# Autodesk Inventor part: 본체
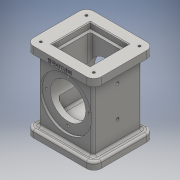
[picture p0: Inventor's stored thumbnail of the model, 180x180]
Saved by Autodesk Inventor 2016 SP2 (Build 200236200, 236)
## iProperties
Created: 2017-08
Part Number: 본체
Material: Generic
Document SubType Name: Modeling
Designer: Administrator
Density: 1 g/cm^3
Appearance: Default
Mass: 322.201 g
Surface Area: 648.794 cm^2
Volume: 322.201 cm^3
Author: Administrator
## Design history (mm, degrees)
sketch "스케치1"
  geometry: L1 (0, 0)-(92, 0); L2 (92, 0)-(92, -82); L3 (92, -82)-(0, -82); L4 (0, -82)-(0, 0)
  constraints: 8 end point, 2 parallel, 1 horizontal, 1 perpendicular
  dimensions: "d0" = 92 distance between parallel lines of L2 L4; "d1" = 82 distance between parallel lines of L3 L1
extrude "돌출1" new body sketch "스케치1" distance "d2" = 10; taper "d3" = 0 deg
sketch "스케치3"
  geometry: L1 (9, -8)-(83, -8); L2 (83, -8)-(83, -74); L3 (83, -74)-(9, -74); L4 (9, -74)-(9, -8); L5 (46, 14.875)-(46, -113.315); L6 (-13.466, -41)-(112.053, -41); L7 (92, 0)-(0, 0) reference; L8 (0, 0)-(0, -82) reference; 2 further points
  constraints: 12 end point, 2 horizontal, 2 midpoint, 2 parallel, 2 point on line, 1 perpendicular, 1 vertical, 2 other
  dimensions: "d6" = 74 distance between parallel lines of L2 L4; "d7" = 66 distance between parallel lines of L3 L1
extrude "돌출2" join sketch "스케치3" distance "d8" = 88; taper "d9" = 0 deg
sketch "스케치4"
  geometry: L1 (0, 0)-(0, -82) reference; L2 (92, -82)-(92, 0) reference; L3 (0, 0)-(92, 0); L4 (92, 0)-(92, -82); L5 (92, -82)-(0, -82); L6 (0, -82)-(0, 0)
  constraints: 8 end point, 2 parallel, 1 horizontal, 1 perpendicular
extrude "돌출3" join sketch "스케치4" distance "d10" = 10; taper "d11" = 0 deg
sketch "스케치5"
  geometry: L1 (-22, -65)-(-70, -65); L2 (-70, -65)-(-70, -17); L3 (-70, -17)-(-22, -17); L4 (-22, -17)-(-22, -65); L5 (-46, -97.263)-(-46, 16.227); L6 (13.409, -41)-(-111.741, -41); L7 (-92, -82)-(0, -82) reference; L8 (0, -82)-(0, 0) reference; 2 further points
  constraints: 12 end point, 2 horizontal, 2 midpoint, 2 parallel, 2 point on line, 1 perpendicular, 1 vertical, 2 other
  dimensions: "d12" = 48 distance between parallel lines of L2 L4; "d13" = 48 distance between parallel lines of L3 L1
extrude "돌출4" cut sketch "스케치5" distance "d14" = 16; taper "d15" = 0 deg
sketch "스케치6"
  geometry: L1 (83, -10)-(-9, -10) reference; C1 r 35 at (37, 44); 1 further point
  constraints: 1 centre point, 1 midpoint, 1 vertical alignment
  dimensions: "d16" = 70 diameter of C1; "d17" = 54 distance from line of L1 C1.centre
extrude "돌출5" cut sketch "스케치6" distance "d18" = 3; taper "d19" = 0 deg
sketch "스케치7"
  geometry: L1 (-9, 10)-(83, 10) reference; C1 r 35 at (37, -44); 1 further point
  constraints: 1 centre point, 1 midpoint, 1 vertical alignment
  dimensions: "d20" = 70 diameter of C1; "d21" = 54 distance from line of L1 C1.centre
extrude "돌출6" cut sketch "스케치7" distance "d22" = 3; taper "d23" = 0 deg
sketch "스케치8"
  geometry: L1 (46, -54)-(-46, -54) reference; C1 r 24 at (0, 2); 1 further point
  constraints: 1 centre point, 1 midpoint, 1 vertical alignment
  dimensions: "d24" = 48 diameter of C1; "d25" = 56 distance from line of L1 C1.centre
extrude "돌출7" cut sketch "스케치8" stored distance "d26" = 3; taper "d27" = 0 deg
sketch "스케치9"
  geometry: L1 (20, -15)-(72, -15); L2 (72, -15)-(72, -67); L3 (72, -67)-(20, -67); L4 (20, -67)-(20, -15); L5 (46, 9.933)-(46, -105.516); L6 (-12.497, -41)-(110.193, -41); L7 (92, 0)-(0, 0) reference; L8 (0, 0)-(0, -82) reference; 2 further points
  constraints: 12 end point, 2 horizontal, 2 midpoint, 2 parallel, 2 point on line, 1 perpendicular, 1 vertical, 2 other
  dimensions: "d28" = 52 distance between parallel lines of L3 L1; "d29" = 52 distance between parallel lines of L2 L4
extrude "돌출8" cut sketch "스케치9" distance "d30" = 8; taper "d31" = 0 deg
sketch "스케치10"
  geometry: L1 (24, -19)-(68, -19); L2 (68, -19)-(68, -63); L3 (68, -63)-(24, -63); L4 (24, -63)-(24, -19); L5 (46, 16.944)-(46, -107.049); L6 (-13.372, -41)-(115.449, -41); L7 (92, 0)-(0, 0) reference; L8 (0, 0)-(0, -82) reference; 2 further points
  constraints: 12 end point, 2 horizontal, 2 midpoint, 2 parallel, 2 point on line, 1 perpendicular, 1 vertical, 2 other
  dimensions: "d32" = 44 distance of L1.start L1.end; "d33" = 44 distance between parallel lines of L3 L1
extrude "돌출9" cut sketch "스케치10" distance "d34" = 74; taper "d35" = 0 deg
sketch "스케치12"
  geometry: L1 (46, -54)-(-46, -54) reference; A1 r 29 centre (0, 2) between (0, 31) and (29, 2); 3 further points
  constraints: 4 point on circle, 3 vertical alignment, 2 horizontal alignment, 1 centre point, 1 midpoint
  dimensions: "d36" = 58 diameter of A1; "d37" = 56 distance from line of L1 A1.centre
hole "구멍1" sketch "스케치12" at (0, 31), (29, 2), (-29, 2), (0, -27) diameter "d38" = 3.242; stored, may be unused: countersink angle "d42" = 90 deg, drill point angle "d44" = 118 deg; dims "d39" = 4, "d40" = 4, "d41" = 2, "d43" = 6
sketch "스케치13"
  geometry: L1 (-46, 54)-(46, 54) reference; C1 r 29 at (0, -2); C2 r 1.621 at (0, -31) reference; C3 r 1.621 at (-29, -2) reference; C4 r 1.621 at (29, -2) reference; C5 r 1.621 at (0, 27) reference; 5 further points
  constraints: 4 coincident, 1 centre point, 1 midpoint, 1 vertical alignment
  dimensions: "d45" = 58 diameter of C1; "d46" = 56 distance from line of L1 C1.centre
hole "구멍2" sketch "스케치13" at (0, -31), (-29, -2), (29, -2), (0, 27) diameter "d47" = 3.242; stored, may be unused: countersink angle "d51" = 90 deg, drill point angle "d53" = 118 deg; dims "d48" = 4, "d49" = 4, "d50" = 2, "d52" = 6
sketch "스케치14"
  geometry: L1 (10, 74)-(10, -8) reference; 5 further points
  constraints: 4 midpoint, 3 horizontal alignment
  dimensions: "d54" = 38 distance from line of L1 point (-28, 33)
hole "구멍3" sketch "스케치14" at (-28, 33) diameter "d56" = 4.134; stored, may be unused: countersink angle "d60" = 90 deg, drill point angle "d62" = 118 deg; dims "d57" = 10, "d58" = 4, "d59" = 2, "d61" = 14.2
sketch "스케치15"
  geometry: L1 (10, 74)-(10, -8) reference; 2 further points
  constraints: 1 horizontal alignment, 1 midpoint
  dimensions: "d63" = 80 distance from line of point (-70, 33) L1
hole "구멍4" sketch "스케치15" at (-70, 33) diameter "d64" = 4.134; stored, may be unused: countersink angle "d68" = 90 deg, drill point angle "d70" = 118 deg; dims "d65" = 10, "d66" = 4, "d67" = 2, "d69" = 14.2
sketch "스케치16"
  geometry: L1 (46, 21.815)-(46, -83.748); L2 (-19.316, -41)-(104.246, -41); L3 (92, 0)-(0, 0) reference; L4 (0, 0)-(0, -82) reference; 6 further points
  constraints: 4 end point, 2 midpoint, 2 point on line, 2 vertical alignment, 1 horizontal, 1 symmetric about line, 1 vertical
  dimensions: "d75" = 72 distance of point (82, -10.06) point (10, -10.06); "d76" = 62 distance of point (10, -72.06) point (10, -10.06); "d77" = 62 distance of point (82, -72.06) point (82, -10.06)
hole "구멍5" sketch "스케치16" at (10, -10.06), (82, -10.06), (82, -72.06), (10, -72.06) diameter "d78" = 3.242; stored, may be unused: countersink angle "d82" = 90 deg, drill point angle "d84" = 118 deg; dims "d79" = 4, "d80" = 4, "d81" = 2, "d83" = 6
sketch "스케치17"
  geometry: C1 r 1.621 at (-10, -72.06) reference; C2 r 1.621 at (-82, -72.06) reference; C3 r 1.621 at (-10, -10.06) reference; C4 r 1.621 at (-82, -10.06) reference; 5 further points
  constraints: 4 coincident
hole "구멍6" sketch "스케치17" at (-10, -72.06), (-82, -72.06), (-10, -10.06), (-82, -10.06) diameter "d85" = 3.242; stored, may be unused: countersink angle "d89" = 90 deg, drill point angle "d91" = 118 deg; dims "d86" = 4, "d87" = 4, "d88" = 2, "d90" = 6
sketch "스케치18"
  geometry: L1 (0, 0)-(0, 10) reference; L2 (92, 0)-(0, 0) reference; 3 further points
  constraints: 1 coincident, 1 other
  dimensions: "d92" = 46 distance from line of point (46, 4) L1; "d93" = 4 distance from line of point (46, 4) L2
feature "엠보싱1" sketch "스케치18" dims "d0" = 92, "d1" = 82, "d94" = 0.5, "d95" = 0
fillet "모깎기1" dims "d96" = 10
fillet "모깎기3" dims "d101" = 3
fillet "모깎기4" dims "d102" = 3
fillet "모깎기5" dims "d103" = 3
fillet "모깎기6" dims "d104" = 3
chamfer "모따기2" distance "d106" = 1; stored, may be unused: second distance "d107" = 2, angle "d108" = 45 deg
fillet "모깎기8" dims "d109" = 3
fillet "모깎기10" dims "d111" = 3
node "솔리드1"
